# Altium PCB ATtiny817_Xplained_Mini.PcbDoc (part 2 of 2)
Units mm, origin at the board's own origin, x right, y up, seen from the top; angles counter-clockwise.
Board outline 60 x 75 mm, 4 copper layers (Top Layer, Ground Plane, Power Plane, Bottom Layer), stack 0.778 mm thick; 64 components, 81 nets, 498 pads, 125 vias.
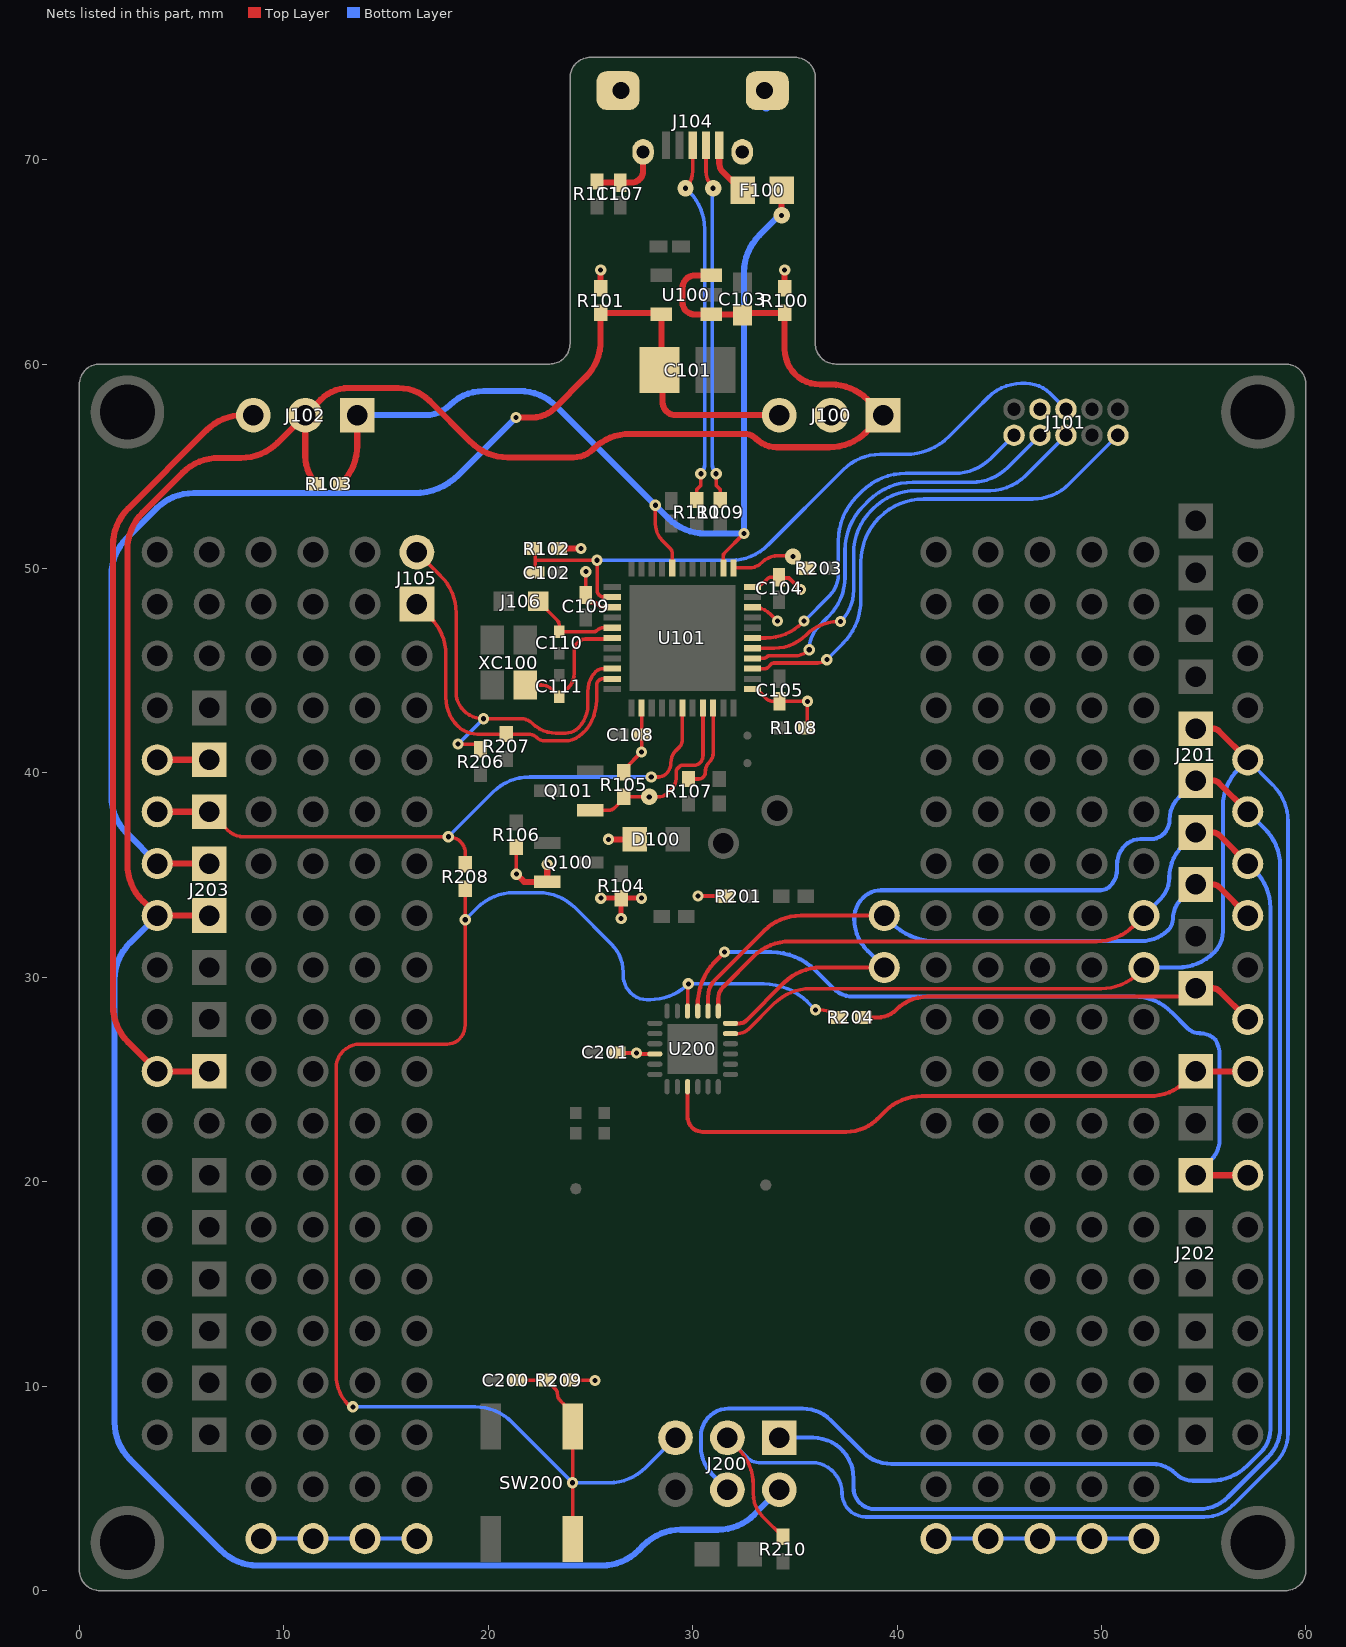
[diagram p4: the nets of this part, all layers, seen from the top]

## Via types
v1: diameter 0.55, hole 0.25, Top Layer to Bottom Layer, 103 vias
v2: diameter 0.55/0.8 (per signal layer), hole 0.25, Top Layer to Bottom Layer, tented top, 22 vias

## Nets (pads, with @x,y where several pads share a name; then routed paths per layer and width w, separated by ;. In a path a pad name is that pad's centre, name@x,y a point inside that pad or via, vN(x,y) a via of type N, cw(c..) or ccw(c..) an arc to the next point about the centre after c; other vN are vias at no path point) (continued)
PB7: J202.8 pad.12@57.15,25.4 U200.9 | length 30.2
  Top Layer w0.2: U200.9@29.75,24.64 29.75,23.177 ccw(c30.487,23.177) 30.487,22.441 37.504,22.441 ccw(c37.504,24.619) 38.602,22.737 ccw(c37.504,24.619) 39.045,23.079 39.408,23.442 cw(c41.204,21.646) 41.204,24.186 52.344,24.186 ccw(c52.344,26.726) 54.14,24.93 J202.8@54.61,25.4
  Top Layer w0.3: J202.8@54.61,25.4 pad.12@57.15,25.4
PC0_SPI_SCK: J200.3@31.7,7.48 J201.6@54.61,42.164 pad.10@52.07,30.48 pad.12@57.15,40.64 R210.2 U200.17 | length 108.2
  Top Layer w0.175: J200.3@31.7,7.48 32.219,6.961 cw(c30.423,5.164) 32.963,5.164 32.963,4.744 ccw(c34.554,4.744) 33.429,3.62 R210.2@34.417,2.632 ; U200.17@31.86,27.25 32.201,27.25 ccw(c32.201,28.012) 32.739,27.473 33.971,28.705 cw(c35.767,26.909) 35.767,29.449 49.987,29.449 ccw(c49.987,31.989) 51.783,30.193 pad.10@52.07,30.48
  Top Layer w0.3: J201.6@54.61,42.164 55.457,42.164 cw(c55.457,41.755) 55.746,42.044 pad.12@57.15,40.64
  Bottom Layer w0.175: J200.3@31.7,7.48 32.704,6.476 ccw(c33.225,6.997) 33.225,6.261 35.819,6.261 cw(c35.819,4.775) 37.305,4.775 ccw(c38.479,4.775) 38.479,3.601 55.027,3.601 ccw(c55.027,5.582) 56.428,4.181 58.542,6.295 ccw(c57.141,7.696) 59.122,7.696 59.122,37.616 ccw(c56.582,37.616) 58.378,39.412 pad.12@57.15,40.64
  Bottom Layer w0.2: pad.10@52.07,30.48 53.718,30.48 ccw(c53.718,33.02) 55.514,31.224 ccw(c54.492,32.247) 55.938,32.247 55.938,38.376 cw(c58.478,38.376) pad.12@56.682,40.172
PC1_SPI_MISO: J200.1@34.24,7.48 J201.5@54.61,39.624 pad.12@57.15,38.1 pad.@39.37,30.48 U200.18 | length 94.6
  Top Layer w0.2: U200.18@31.86,27.75 32.282,27.75 ccw(c32.282,28.249) 32.635,27.896 34.475,29.736 cw(c36.271,27.94) 36.271,30.48 pad.@39.37,30.48
  Top Layer w0.3: J201.5@54.61,39.624 55.457,39.624 cw(c55.457,39.215) 55.746,39.504 pad.12@57.15,38.1
  Bottom Layer w0.2: J200.1@34.24,7.48 35.885,7.48 cw(c35.885,5.499) 37.866,5.499 37.866,5.038 ccw(c38.918,5.038) 38.918,3.986 54.773,3.986 ccw(c54.773,5.968) 56.173,4.567 58.154,6.547 ccw(c56.753,7.948) 58.735,7.948 ; pad.@39.37,30.48 38.549,31.301 cw(c40.11,32.862) 37.902,32.862 cw(c39.355,32.862) 38.328,33.889 cw(c39.216,33.001) 39.216,34.257 49.943,34.257 ccw(c49.943,34.928) 50.417,34.454 ccw(c49.594,35.277) 50.758,35.277 50.758,35.513 cw(c52.079,35.513) 51.145,36.447 cw(c51.905,35.686) 51.905,36.762 52.42,36.762 ccw(c52.42,37.636) 53.039,37.018 ccw(c52.332,37.724) 53.331,37.724 cw(c54.831,37.724) 53.771,38.785 J201.5@54.61,39.624 ; pad.12@57.15,38.1 57.991,37.259 cw(c56.195,35.463) 58.735,35.463 58.735,8.026
PC2_SPI_MOSI: J200.4@31.7,4.94 J201.4@54.61,37.084 pad.10@52.07,33.02 pad.12@57.15,35.56 U200.19 | length 93.3
  Top Layer w0.2: U200.19@31.25,28.36 31.25,28.944 cw(c32.092,28.944) 31.497,29.539 32.976,31.018 cw(c34.772,29.222) 34.772,31.762 49.76,31.762 ccw(c49.76,34.302) 51.556,32.506 pad.10@52.07,33.02
  Top Layer w0.3: J201.4@54.61,37.084 55.457,37.084 cw(c55.457,36.675) 55.746,36.964 pad.12@57.15,35.56
  Bottom Layer w0.2: J200.4@31.7,4.94 30.983,5.657 cw(c32.384,7.058) 30.402,7.058 30.402,7.548 cw(c31.76,7.548) 31.76,8.906 35.369,8.906 cw(c35.369,6.925) 36.77,8.326 38.32,6.776 ccw(c39.721,8.177) 39.721,6.196 52.49,6.196 cw(c52.49,4.607) 53.613,5.731 ccw(c54.474,6.591) 54.474,5.374 55.34,5.374 ccw(c55.34,7.914) 57.136,6.118 57.793,6.776 ccw(c56.671,7.898) 58.258,7.898 58.258,33.4 ccw(c55.718,33.4) 57.514,35.196 pad.12@57.15,35.56 ; pad.10@52.07,33.02 52.877,33.827 ccw(c51.823,34.881) 53.313,34.881 cw(c55.502,34.881) 53.954,36.428 J201.4@54.61,37.084
PC3_SPI_SS: J201.3@54.61,34.544 pad.12@57.15,33.02 pad.@39.37,33.02 U200.20 | length 32
  Top Layer w0.2: U200.20@30.75,28.36 30.75,29.053 cw(c31.914,29.053) 31.091,29.876 33.491,32.276 cw(c35.287,30.48) 35.287,33.02 pad.@39.37,33.02 pad.@39.846,33.496
  Top Layer w0.3: J201.3@54.61,34.544 55.457,34.544 cw(c55.457,34.135) 55.746,34.424 pad.12@57.15,33.02
  Bottom Layer w0.2: pad.@39.37,33.02 39.728,32.662 ccw(c41.883,34.817) 41.883,31.769 51.933,31.769 ccw(c51.933,33.664) 53.273,32.324 ccw(c52.754,32.843) 53.488,32.843 cw(c54.885,32.843) 53.897,33.831 J201.3@54.61,34.544
PC4_PWM_W4: J202.6 pad.12@57.15,20.32 U200.21 | length 39.6
  Top Layer w0.2: U200.21@30.25,28.36 U200.21@30.25,28.666 ; 30.25,28.874 U200.21@30.25,28.666 ; 30.994,30.67 31.062,30.737 ; 31.348,31.024 31.062,30.737 ; v1(31.556,31.235) 31.143,30.822 ccw(c33.298,28.666) 31.062,30.737 ; J202.6@54.175,20.755 J202.6@54.61,20.32 ; U200.21@30.25,28.666 cw(c33.298,28.666) 31.062,30.737
  Top Layer w0.3: J202.6@54.61,20.32 pad.12@57.15,20.32
  Bottom Layer w0.2: v1(31.556,31.235) 33.844,31.235 cw(c33.844,28.187) 35.999,30.342 36.891,29.45 ccw(c37.847,30.407) 37.847,29.054 51.615,29.054 cw(c51.615,26.514) 53.411,28.31 54.213,27.508 ccw(c54.804,28.099) 54.804,27.264 54.824,27.264 cw(c54.824,26.219) 55.562,26.958 cw(c54.356,26.204) 55.779,26.204 55.779,22.072 cw(c54.371,22.072) 55.366,21.076 J202.6@54.61,20.32
PC5_BTN: C200.2 J200.5@29.16,7.48 R204.1 R208.1 R209.1 SW200.3 SW200.4 U200.22 | length 82.1
  Top Layer w0.175: v1(13.375,8.991) cw(c13.375,9.281) 13.171,9.076 cw(c14.656,10.562) 12.555,10.562 12.555,25.578 cw(c13.69,25.578) 12.888,26.38 cw(c13.734,25.534) 13.734,26.731 17.997,26.731 ccw(c17.997,27.558) 18.582,26.973 ccw(c17.882,27.673) 18.872,27.673 18.872,31.631 ; 18.875,31.633 v1(18.875,32.814) R208.1@18.875,34.325 ; C200.2@21.4,10.3 R209.1@22.85,10.3 23.285,9.865 cw(c23.043,9.624) 23.384,9.624 ccw(c23.839,9.624) 23.518,9.303 23.651,9.17 cw(c22.506,8.025) SW200.4@24.125,8.025 v1(24.125,5.275) SW200.3@24.125,2.525 ; U200.22@29.75,28.36 v1@29.75,29.554 ; v1(36.003,28.408) 36.24,28.408 cw(c36.24,27.139) R204.1@37.138,28.036
  Bottom Layer w0.175: v1(13.375,8.991) 19.357,8.991 cw(c19.357,6.451) 21.153,8.247 v1(24.125,5.275) 25.903,5.275 ccw(c25.903,7.815) 27.699,6.019 J200.5@29.16,7.48 ; v1(18.875,32.814) 19.459,33.398 cw(c21.255,31.602) 21.255,34.142 22.457,34.142 cw(c22.457,31.602) 24.253,33.398 26.033,31.618 cw(c24.671,30.256) 26.597,30.256 26.597,30.122 ccw(c27.847,30.122) 26.963,29.238 ccw(c27.762,30.036) 27.762,28.907 27.919,28.907 ccw(c27.919,31.549) 29.054,29.163 ccw(c27.919,31.549) v1(29.787,29.681) 33.468,29.681 cw(c33.468,26.633) 35.622,28.789 cw(c33.468,26.633) 35.624,28.788 v1(36.003,28.408)
PC5_PWM_W5: J201.1@54.61,29.464 pad.12@57.15,27.94 R204.2 | length 19.8
  Top Layer w0.2: R204.2@38.338,28.036 39.039,28.036 ccw(c39.039,29.351) 39.969,28.421 cw(c41.495,26.895) 41.495,29.054 53.62,29.054 ccw(c53.62,30.454) J201.1@54.61,29.464
  Top Layer w0.3: J201.1@54.61,29.464 55.457,29.464 cw(c55.457,29.055) 55.746,29.344 pad.12@57.15,27.94
PD2_UART_RXD1: J105.2@16.51,50.8 R206.1 U101.20 | length 21.3
  Top Layer w0.175: J105.2@16.51,50.8 17.681,49.629 cw(c15.885,47.833) 18.425,47.833 18.425,43.955 ccw(c19.705,43.955) 18.8,43.05 ccw(c19.766,44.016) v1(19.766,42.65) 21.607,42.65 cw(c21.607,41.882) 22.15,42.425 ccw(c23.311,43.586) 23.311,41.944 23.783,41.944 ccw(c23.783,42.831) 24.41,42.204 ccw(c23.288,43.326) 24.412,42.205 ccw(c23.288,43.326) 24.875,43.326 24.875,43.998 cw(c26.248,43.998) 25.277,44.968 cw(c25.595,44.651) 25.595,45.1 U101.20@26.075,45.1 ; v1(18.525,41.409) 19.366,41.409 R206.1@19.625,41.15
  Bottom Layer w0.175: v1(18.525,41.409) v1(19.766,42.65)
PD3_UART_TXD1: J105.1@16.51,48.26 R207.1 U101.21 | length 16.5
  Top Layer w0.175: J105.1@16.51,48.26 17.181,47.589 cw(c15.385,45.793) 17.925,45.793 17.925,43.688 ccw(c19.888,43.688) 18.5,42.3 ccw(c19.466,43.266) 19.466,41.9 R207.1@20.875,41.9 21.964,41.9 cw(c21.964,41.319) 22.374,41.73 ccw(c22.766,42.122) 22.766,41.568 23.74,41.568 ccw(c23.74,42.781) 24.598,41.923 24.6,41.925 ; 24.602,41.923 24.787,42.108 ccw(c22.945,43.576) 24.8,42.125 ccw(c22.945,43.576) 25.3,43.576 25.3,44.262 cw(c25.662,44.262) 25.406,44.518 cw(c25.604,44.32) 25.604,44.6 U101.21@26.075,44.6
POWER_ENABLE: Q101.1 R105.1 U101.30 | length 11.1
  Top Layer w0.175: Q101.1@24.985,38.17 25.902,38.17 ccw(c25.902,38.538) 25.962,38.175 ccw(c25.902,38.538) 26.162,38.278 26.565,38.681 ccw(c26.422,38.825) R105.1@26.625,38.825 v2(27.878,38.825) 28.306,38.825 ccw(c28.306,39.547) 28.817,39.036 28.967,39.187 ccw(c28.434,39.719) 29.187,39.719 29.187,40.016 cw(c29.507,40.016) 29.281,40.242 29.335,40.296 cw(c29.532,40.099) 29.532,40.378 30.09,40.378 ccw(c30.09,40.754) 30.356,40.488 ccw(c29.997,40.847) 30.505,40.847 30.505,43.17 U101.30@30.5,43.175 30.5,41.501
RESET_SENSE: J203.3@6.35,38.1 pad.0@3.81,38.1 R208.2 U101.28 | length 31.8
  Top Layer w0.175: J203.3@6.35,38.1 7.239,37.211 ccw(c8.05,38.022) 8.05,36.875 v1(18.046,36.875) cw(c18.046,36.021) 18.65,36.625 cw(c18.107,36.082) 18.875,36.082 R208.2@18.875,35.525 ; v1(27.975,39.8) 28.334,39.8 ccw(c28.334,40.326) 28.706,39.954 ccw(c28.163,40.497) 28.931,40.497 cw(c29.78,40.497) 29.18,41.097 29.353,41.27 ccw(c28.997,41.625) 29.5,41.625 U101.28@29.5,43.175
  Top Layer w0.3: pad.0@3.81,38.1 J203.3@6.35,38.1
  Bottom Layer w0.175: v1(18.046,36.875) 20.227,39.056 cw(c22.024,37.26) 22.024,39.8 v1(27.975,39.8)
S\R\S\T\: C102.2 J101.6 R102.1 U101.13 | length 33.1
  Top Layer w0.175: R102.1@22.25,50.975 cw(c22.129,50.854) 22.3,50.854 22.3,50.4 ; C102.2@22.3,49.8 22.3,50.4 ; U101.13@26.075,48.6 25.666,48.6 cw(c25.666,48.941) 25.425,48.7 cw(c25.666,48.941) 25.325,48.941 v1(25.325,50.4) 22.3,50.4
  Bottom Layer w0.175: v1(25.325,50.4) 31.885,50.4 ccw(c31.885,52.94) 33.682,51.144 37.37,54.833 cw(c39.166,53.036) 39.166,55.576 40.401,55.576 ccw(c40.401,58.624) 42.556,56.469 43.844,57.757 44.472,58.385 cw(c46.085,56.773) 46.085,59.053 46.298,59.053 cw(c46.298,57.379) 47.482,58.563 J101.6@48.26,57.785
SHIELD: C107.2 J104.6@33.512,73.375 J104.7@26.488,73.375 J104.8@32.425,70.375 J104.9@27.575,70.375 R111.1 | length 5.1
  Top Layer w0.3: R111.1@25.315,68.926 ccw(c25.436,69.047) 25.436,68.876 C107.2@26.458,68.876 27.008,68.876 ccw(c27.008,69.445) 27.411,69.043 ccw(c27.015,69.439) 27.575,69.439 J104.9@27.575,70.375 ; J104.6@33.6,72.585 J104.6@33.6,73.375
  Bottom Layer w0.5: J104.6@33.6,72.602 J104.6@33.6,73.375
STATUS_LED: R107.2 U101.31 | length 4.3
  Top Layer w0.175: R107.2@29.8,39.7 30.306,39.7 ccw(c30.306,39.995) 30.515,39.787 ccw(c30.259,40.042) 30.621,40.042 cw(c31.341,40.042) 30.648,40.238 cw(c31.341,40.042) 30.832,40.552 ccw(c30.426,40.958) 30.908,40.645 ccw(c30.426,40.958) 31,40.958 U101.31@31,43.175
TCK: J101.1 U101.39 | length 18.4
  Top Layer w0.175: U101.39@32.925,46.6 33.573,46.6 ccw(c33.573,49.14) 35.369,47.344 v1(35.45,47.425)
  Bottom Layer w0.175: v1(35.45,47.425) 36.693,48.668 ccw(c35.653,49.709) 37.125,49.709 37.125,51.358 cw(c40.173,51.358) 38.017,53.513 38.267,53.762 cw(c40.422,51.607) 40.422,54.655 42.817,54.655 ccw(c42.817,57.172) 44.597,55.392 J101.1@45.72,56.515
TDI: J101.9 U101.36 | length 26.2
  Top Layer w0.175: U101.36@32.925,45.1 33.525,45.1 ccw(c33.525,45.341) 33.696,45.171 33.85,45.325 ; 33.85,45.325 cw(c33.971,45.204) 33.971,45.375 36.128,45.375 ccw(c36.128,45.972) 36.55,45.55 v1(36.562,45.538)
  Bottom Layer w0.175: v1(36.562,45.538) 37.334,46.31 ccw(c35.179,48.465) 37.335,46.311 ccw(c35.179,48.465) 38.043,47.423 ccw(c35.179,48.465) 38.227,48.465 38.227,50.326 cw(c41.275,50.326) 39.119,52.481 39.143,52.505 cw(c41.298,50.349) 41.298,53.397 46.63,53.397 ccw(c46.63,55.937) 47.102,53.442 ; J101.9@50.8,56.515 48.426,54.141 ; 47.102,53.442 ccw(c46.63,55.937) 48.426,54.141 ; 47.102,53.442 ccw(c46.63,55.937) 48.426,54.141
TDO: J101.3 U101.37 | length 22.5
  Top Layer w0.175: U101.37@32.925,45.6 33.444,45.6 ccw(c33.444,45.856) 33.625,45.675 cw(c33.746,45.554) 33.746,45.725 34.976,45.725 ccw(c34.976,46.749) v1(35.7,46.025)
  Bottom Layer w0.175: v1(35.7,46.025) cw(c37.33,46.025) 36.177,47.177 36.5,47.5 ccw(c34.75,49.25) 36.6,47.606 36.653,47.659 ccw(c34.73,49.582) 37.45,49.582 37.45,50.891 cw(c40.498,50.891) 38.342,53.047 38.62,53.324 cw(c40.775,51.169) 40.775,54.217 43.654,54.217 ; J101.3@46.99,56.515 45.426,54.951 ; 43.654,54.217 ccw(c43.654,56.722) 45.426,54.951 ; 43.654,54.217 ccw(c43.654,56.722) 45.426,54.951
TMS: J101.5 U101.38 | length 21.3
  Top Layer w0.175: U101.38@32.925,46.1 33.981,46.1 ccw(c33.981,48.319) 35.55,46.75 cw(c37.119,45.181) 37.119,47.4 v1(37.236,47.4)
  Bottom Layer w0.175: v1@37.237,47.401 ccw(c35.698,48.938) 37.672,48.025 ccw(c35.698,48.938) 37.873,48.938 37.873,50.722 cw(c40.921,50.722) 38.766,52.877 38.804,52.914 cw(c40.959,50.759) 40.959,53.807 44.5,53.807 ccw(c44.5,56.347) 44.556,53.808 ccw(c44.5,56.347) 46.296,54.551 J101.5@48.26,56.515
UPDI: R203.1 U101.1 | length 4.1
  Top Layer w0.175: U101.1@32,50.025 32.736,50.025 ccw(c32.736,50.964) 33.4,50.3 cw(c34.185,49.515) 34.185,50.625 34.55,50.625 cw(c34.55,49.9) 35.275,49.9 R203.1@35.55,49.9
  other v2: 34.908,50.583
USB_VBUS: F100.1 J104.1 | length 2.7
  Top Layer w0.3: J104.1@31.3,70.7 31.3,69.822 ccw(c31.897,69.822) 31.475,69.4 32.322,68.553 ccw(c32.45,68.681) F100.1@32.45,68.5
USBD_N: J104.2 R109.1 | length 17.6
  Top Layer w0.18: J104.2@30.65,70.7 30.65,69.445 ccw(c31.845,69.445) v2(31,68.6) ; v1(31.15,54.635) 31.15,54.062 31.35,53.862 R109.1@31.35,53.35
  Bottom Layer w0.18: v2(31,68.6) ccw(c31.084,68.516) 30.965,68.516 30.965,55.082 ccw(c31.597,55.082) v1(31.15,54.635) v1@31.15,54.684
USBD_P: J104.3 R110.1 | length 17.9
  Top Layer w0.18: v2(29.65,68.6) ccw(c28.805,69.445) 30,69.445 J104.3@30,70.7 ; R110.1@30.2,53.35 30.2,53.862 30.4,54.062 v1(30.4,54.635)
  Bottom Layer w0.18: v2(29.65,68.6) 29.841,68.409 cw(c28.045,66.613) 30.585,66.613 30.585,55.082 cw(c29.953,55.082) v1(30.4,54.635)
VCC_BOARD: C104.2 C105.1 C108.2 C109.1 D100.2 J100.2 J101.4 Q100.2 R100.1 R101.2 R102.2 R105.2 R106.2 R108.2 U101.14 U101.24 U101.34 U101.42 U101.44 | length 22.9
  Top Layer w0.175: v1(21.375,35.046) R106.2@21.375,36.375 ; v1(24.775,49.844) C109.1@24.775,48.7 24.775,48.336 25.201,48.336 cw(c25.201,48.175) 25.315,48.289 25.443,48.16 ccw(c25.589,48.306) 25.589,48.1 U101.14@26.075,48.1 ; R105.2@26.625,40.025 cw(c26.916,40.025) 26.71,40.231 v1(27.5,41.021) C108.2@27.5,41.875 U101.24@27.5,43.175 ; U101.34@32.925,44.1 cw(c32.925,43.617) 33.266,43.959 33.575,43.65 ccw(c33.937,44.012) 33.937,43.5 C105.1@34.25,43.5 v1(35.615,43.5) 35.615,42.356 cw(c35.394,42.356) R108.2@35.55,42.2 ; U101.42@32.925,48.1 32.98,48.1 cw(c32.98,46.905) 33.825,47.75 v1(34.15,47.425) ; U101.44@32.925,49.1 ccw(c32.925,49.926) 33.509,49.342 33.661,49.493 cw(c33.858,49.296) 33.858,49.575 C104.2@34.225,49.575
  Top Layer w0.2: C104.2@34.225,49.575 ccw(c34.303,49.653) 34.303,49.543 34.631,49.543 cw(c34.631,49.357) 34.762,49.488 v1(35.275,48.975)
  Top Layer w0.3: v1(21.375,35.046) 21.751,34.67 Q100.2@22.885,34.67 v1(22.885,35.515) ; R102.2@23.45,50.975 v1(24.54,50.975) ; R101.2@25.5,63.7 v1(25.5,64.602) ; v1(25.885,36.75) D100.2@27.175,36.75 ; R100.1@34.5,63.7 v1(34.5,64.603)
  Bottom Layer w0.3: v1(34.5,64.603) cw(c34.557,64.603) v1@34.557,64.66
VCC_P3V3: C101.1 J100.3 J203.4@6.35,35.56 pad.0@3.81,35.56 R101.1 U100.5 | length 61.8
  Top Layer w0.3: pad.0@3.81,35.56 J203.4@6.35,35.56 ; v1(21.354,57.383) 22.142,57.383 ccw(c22.142,58.952) 23.252,57.842 24.756,59.347 ccw(c22.96,61.143) 25.5,61.143 R101.1@25.5,62.5 U100.5@28.398,62.5 ; J100.3@34.235,57.5 29.174,57.5 cw(c29.174,58.145) 28.529,58.145 28.529,59.121 ccw(c28.43,59.121) 28.43,59.22 28.43,59.714 ccw(c28.339,59.805) 28.468,59.805 U100.5@28.468,62.431 ; U100.5@28.398,62.5 cw(c28.398,62.431) U100.5@28.468,62.431 ; U100.5@28.398,62.5 U100.5@28.468,62.431
  Bottom Layer w0.3: pad.0@3.81,35.56 2.308,37.062 cw(c4.104,38.858) 1.564,38.858 1.564,49.674 cw(c4.104,49.674) 2.308,51.47 3.781,52.943 cw(c5.577,51.147) 5.577,53.687 16.395,53.687 ccw(c16.395,56.735) 18.551,54.58 v1(21.354,57.383)
VCC_P5V0: C103.1 J100.1 J102.2 J200.2@34.24,4.94 J203.5@6.35,33.02 pad.0@3.81,33.02 R100.2 R103.2 U100.1 U100.3 | length 145.6
  Top Layer w0.3: J203.5@6.35,33.02 pad.0@3.81,33.02 3.094,33.736 cw(c4.89,35.532) 2.35,35.532 2.35,50.928 cw(c4.89,50.928) 3.094,52.724 5.038,54.668 cw(c6.834,52.872) 6.834,55.412 7.91,55.412 ccw(c7.91,57.952) 9.706,56.156 J102.2@11.05,57.5 ; R103.2@11.6,54.15 cw(c12.928,55.478) 11.05,55.478 J102.2@11.05,57.5 ; U100.3@30.918,64.337 30.111,64.337 ccw(c30.111,63.73) 29.505,63.73 29.505,63.01 ccw(c30.084,63.01) 30.084,62.431 U100.1@30.918,62.431 32.386,62.431 C103.1@32.436,62.381 cw(c32.724,62.092) 32.724,62.5 R100.2@34.5,62.5 34.5,60.724 ccw(c36.223,60.724) 36.223,59.001 36.762,59.001 cw(c36.762,56.461) 38.558,58.257 J100.1@39.315,57.5 38.49,56.675 cw(c36.694,58.471) 36.694,55.931 34.11,55.931 cw(c34.11,57.375) 33.089,56.354 ccw(c32.533,55.798) 32.533,56.584 26.934,56.584 ccw(c26.934,54.044) 25.138,55.84 cw(c24.16,56.819) 24.16,55.435 20.948,55.435 cw(c20.948,57.975) 19.152,56.179 17.139,58.191 ccw(c15.61,56.662) 15.61,58.825 13.174,58.825 ccw(c13.174,56.896) 11.81,58.26 J102.2@11.05,57.5
  Bottom Layer w0.3: pad.0@3.81,33.02 2.466,31.676 ccw(c4.262,29.88) 1.722,29.88 1.722,8.226 ccw(c4.262,8.226) 2.466,6.43 6.925,1.971 ccw(c8.721,3.768) 8.721,1.228 25.557,1.228 ccw(c25.557,3.768) 27.353,1.971 27.618,2.237 cw(c29.414,0.44) 29.414,2.98 31.228,2.98 ccw(c31.228,5.52) 33.024,3.724 J200.2@34.24,4.94
VCC_TARGET: C201.2 J203.2@6.35,40.64 pad.0@3.81,40.64 pad.2@8.89,2.54 pad.3@11.43,2.54 pad.4@13.97,2.54 pad.5@16.51,2.54 pad.6@41.91,2.54 pad.7@44.45,2.54 pad.8@46.99,2.54 pad.9@49.53,2.54 pad.10@52.07,2.54 R104.2 R201.2 R209.2 U200.4 | length 28.7
  Top Layer w0.175: R209.2@24.05,10.3 25.165,10.3 cw(c25.165,10.215) v1(25.225,10.275)
  Top Layer w0.2: C201.2@26.3,26.3 v1(27.25,26.3) 27.3,26.25 U200.4@28.14,26.25 ; v1(30.265,33.972) R201.2@31.619,33.972
  Top Layer w0.25: v1(25.509,33.873) R104.2@26.502,33.873 ; v1(26.502,32.88) R104.2@26.502,33.873 ; v1(27.495,33.873) R104.2@26.502,33.873
  Top Layer w0.3: pad.0@3.81,40.64 J203.2@6.35,40.64 J203.2@5.669,39.959
  Bottom Layer w0.2: pad.2@8.89,2.54 pad.3@11.43,2.54 pad.4@13.97,2.54 pad.5@16.51,2.54 ; v1@27.25,26.263 v1(27.25,26.3) ; v1@30.226,33.956 cw(c30.265,33.918) v1(30.265,33.972) ; pad.6@41.91,2.54 pad.7@44.45,2.54 pad.8@46.99,2.54 pad.9@49.53,2.54 pad.10@52.07,2.54
VCC_VBUS: F100.2 J102.1 R103.1 U101.2 U101.7 | length 48.4
  Top Layer w0.175: v1(28.175,53.092) 28.175,52.2 ccw(c29.382,52.2) 28.528,51.347 28.9,50.975 cw(c28.659,50.734) 29,50.734 U101.7@29,50.025 ; U101.2@31.5,50.025 31.5,50.629 cw(c31.671,50.629) 31.55,50.75 ; 31.55,50.75 v1(32.512,51.712)
  Top Layer w0.3: R103.1@12.8,54.15 12.846,54.196 ccw(c11.05,55.992) 13.59,55.992 J102.1@13.59,57.5 ; v2(34.35,67.275) F100.2@34.35,68.5
  Bottom Layer w0.3: J102.1@13.59,57.5 16.928,57.5 ccw(c16.928,59.191) 18.124,57.995 cw(c19.773,56.346) 19.773,58.678 21.537,58.678 cw(c21.537,56.138) 23.333,57.934 v1(28.175,53.092) 28.812,52.456 ccw(c30.608,54.252) 30.608,51.712 v1(32.512,51.712) 32.512,64.493 cw(c35.052,64.493) 33.256,66.289 34.241,67.275 v2(34.35,67.275)
VCC_VIN: J102.3 J203.8@6.35,25.4 pad.0@3.81,25.4 | length 39
  Top Layer w0.3: J203.8@6.35,25.4 pad.0@3.81,25.4 2.387,26.823 cw(c4.183,28.619) 1.643,28.619 1.643,51.136 cw(c4.183,51.136) 2.387,52.932 6.211,56.756 cw(c8.007,54.96) 8.007,57.5 J102.3@8.51,57.5
XTAL1: C111.1 U101.17 XC100.1 | length 6.5
  Top Layer w0.175: XC100.1@21.9,44.3 22.598,44.3 cw(c22.598,43.571) 23.113,44.087 C111.1@23.475,43.725 23.923,44.173 ccw(c23.243,44.853) 23.928,44.178 ccw(c23.243,44.853) 24.205,44.853 24.205,46.034 cw(c24.616,46.034) 24.325,46.325 24.409,46.409 cw(c24.75,46.067) 24.75,46.55 25.954,46.55 ccw(c25.954,46.721) U101.17@26.075,46.6
XTAL2: C110.2 J106.2 U101.16 | length 4.7
  Top Layer w0.175: J106.2@22.535,48.365 ccw(c22.45,48.279) J106.2@22.45,48.4 22.45,48.391 23.374,47.467 cw(c23.129,47.223) 23.475,47.223 C110.2@23.475,46.9 25.144,46.9 ccw(c25.144,47.156) 25.325,46.975 cw(c25.627,46.673) 25.627,47.1 U101.16@26.075,47.1
pads on no net: J104.6@33.6,73.375 J104.7@26.4,73.375 J104.8@32.425,70.375 J104.9@27.575,70.375 J105.1@16.51,48.26 J105.2@16.51,50.8 J200.1@34.24,7.48 J200.2@34.24,4.94 J200.3@31.7,7.48 J200.4@31.7,4.94 J200.5@29.16,7.48 J200.6@29.16,4.94 J201.1@54.61,29.464 J201.2@54.61,32.004 J201.3@54.61,34.544 J201.4@54.61,37.084 J201.5@54.61,39.624 J201.6@54.61,42.164 J201.7@54.61,44.704 J201.8@54.61,47.244 J201.9@54.61,49.784 J201.10@54.61,52.324 J203.1@6.35,43.18 J203.2@6.35,40.64 J203.3@6.35,38.1 J203.4@6.35,35.56 J203.5@6.35,33.02 J203.6@6.35,30.48 J203.7@6.35,27.94 J203.8@6.35,25.4 J204.1@6.35,20.32 J204.2@6.35,17.78 J204.3@6.35,15.24 J204.4@6.35,12.7 J204.5@6.35,10.16 J204.6@6.35,7.62
copper on no net: | length 228.6
  Top Layer w0.3: 3.81,22.86 6.35,22.86 ; 3.81,45.72 6.35,45.72 ; 3.81,48.26 6.35,48.26 ; 3.81,50.8 6.35,50.8 ; 8.89,7.62 11.43,7.62 ; 8.89,10.16 11.43,10.16 ; 8.89,12.7 11.43,12.7 ; 8.89,15.24 11.43,15.24 ; 8.89,17.78 11.43,17.78 ; 8.89,20.32 11.43,20.32 ; 8.89,22.86 11.43,22.86 ; 8.89,25.4 11.43,25.4 ; 8.89,27.94 11.43,27.94 ; 8.89,30.48 11.43,30.48 ; 8.89,33.02 11.43,33.02 ; 8.89,35.56 11.43,35.56 ; 8.89,38.1 11.43,38.1 ; 8.89,45.72 11.43,45.72 ; 8.89,48.26 11.43,48.26 13.97,48.26 ; 8.89,50.8 11.43,50.8 13.97,50.8 ; 13.97,7.62 16.51,7.62 ; 13.97,10.16 16.51,10.16 ; 13.97,12.7 16.51,12.7 ; 13.97,15.24 16.51,15.24 ; 13.97,17.78 16.51,17.78 ; 13.97,20.32 16.51,20.32 ; 13.97,22.86 16.51,22.86 ; 13.97,25.4 16.51,25.4 ; 13.97,27.94 16.51,27.94 ; 13.97,30.48 16.51,30.48 ; 13.97,33.02 16.51,33.02 ; 13.97,35.56 16.51,35.56 ; 13.97,38.1 16.51,38.1 ; 13.97,40.64 16.51,40.64 ; 13.97,43.18 16.51,43.18 ; 13.97,45.72 16.51,45.72 ; 41.91,7.62 44.45,7.62 ; 41.91,10.16 44.45,10.16 ; 41.91,22.86 44.45,22.86 ; 41.91,25.4 44.45,25.4 ; 41.91,27.94 44.45,27.94 ; 41.91,30.48 44.45,30.48 ; 41.91,33.02 44.45,33.02 ; 41.91,35.56 44.45,35.56 ; 41.91,38.1 44.45,38.1 ; 41.91,40.64 44.45,40.64 ; 41.91,43.18 44.45,43.18 ; 41.91,45.72 44.45,45.72 ; 41.91,48.26 44.45,48.26 ; 41.91,50.8 44.45,50.8 ; 46.99,7.62 52.07,7.62 ; 46.99,10.16 52.07,10.16 ; 46.99,12.7 52.07,12.7 ; 46.99,15.24 52.07,15.24 ; 46.99,17.78 52.07,17.78 ; 46.99,20.32 52.07,20.32 ; 46.99,22.86 52.07,22.86 ; 46.99,25.4 52.07,25.4 ; 46.99,27.94 52.07,27.94 ; 46.99,30.48 49.53,30.48 ; 46.99,33.02 49.53,33.02 ; 46.99,35.56 52.07,35.56 ; 46.99,38.1 52.07,38.1 ; 46.99,40.64 52.07,40.64 ; 46.99,43.18 52.07,43.18 ; 46.99,45.72 52.07,45.72 ; 46.99,48.26 52.07,48.26 ; 46.99,50.8 52.07,50.8 ; 8.89,40.64 11.43,40.64 8.89,40.64 ; 8.89,43.18 11.43,43.18 8.89,43.18

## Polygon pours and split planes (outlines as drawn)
no net on Top Overlay "Bottom Layer LF-signals-No Net" (solid, pour order 8): 56,0.2 59.2,0.2 ccw(c59.2,0.7) 59.7,0.7 59.7,3.9 ccw(c59.2,3.9) 59.2,4.4 56,4.4 ccw(c56,3.9) 55.5,3.9 55.5,0.7 ccw(c56,0.7) 56,0.2
GND on Top Layer "Top GND" (solid, remove dead copper, pour order 13): 0,0 0,60 24,60 24,75 36,75 36,60 60,60 60,0
SHIELD on Top Layer "Bottom Layer LF-signals-No Net" (solid, remove dead copper, pour order 10): 25.25,69.7 24.92,69.7 cw(c24.92,70.372) 24.249,70.372 24.249,73.749 cw(c25.25,73.749) 25.25,74.75 34.75,74.75 cw(c34.75,73.75) 35.75,73.75 35.75,70.7 cw(c34.75,70.7) 34.75,69.7
GND on Bottom Layer "Bottom GND" (solid, remove dead copper, pour order 15): 0,0 0,60 24,60 24,75 36,75 36,60 60,60 60,0 42.5,0 42.5,21.75 17.525,21.75 17.525,10.75 44.46,10.75 44.46,0
GND on Bottom Layer "Bottom Layer-No Net" (hatched 45Degree grid 2 track 0.2, pour order 19): 17.525,21.75 42.5,21.75 42.5,10.75 17.525,10.75
GND on Bottom Layer "Bottom Filler" (solid, pour order 21): 41.262,11.061 41.262,0 47.081,0 47.081,11.061
PA6_PTC2 on Ground Plane (split plane): 27.005,20.253 27.005,12.244 17.025,12.244 19.014,12.244 19.014,20.253
PA7_PTC3 on Ground Plane (split plane): 41.005,20.253 41.005,12.244 31.025,12.244 33.014,12.244 33.014,20.253
GND on Ground Plane (split plane): 35.096,74.482 35.188,74.454 35.273,74.409 35.348,74.348 35.409,74.273 35.454,74.188 35.482,74.096 35.491,74.012 35.49,74 35.49,61 35.49,60.998 35.499,60.831 35.527,60.664 35.574,60.501 35.639,60.345 35.721,60.196 35.819,60.058 35.932,59.932 36.058,59.819 36.196,59.721 36.345,59.639 36.501,59.574 36.664,59.527 36.831,59.499 36.998,59.49 37,59.49 59,59.49 59.012,59.491 59.096,59.482 59.188,59.454 59.273,59.409 59.348,59.348 59.409,59.273 59.454,59.188 59.482,59.096 59.491,59.012 59.49,59 59.49,1 59.491,0.988 59.482,0.904 59.454,0.812 59.409,0.727 59.348,0.652 59.273,0.591 59.188,0.546 59.096,0.518 59.012,0.509 59,0.51 1,0.51 0.988,0.509 0.904,0.518 0.812,0.546 0.727,0.591 0.652,0.652 0.591,0.727 0.546,0.812 0.518,0.904 0.509,0.988 0.51,1 0.51,59 0.509,59.012 0.518,59.096 0.546,59.188 0.591,59.273 0.652,59.348 0.727,59.409 0.812,59.454 0.904,59.482 0.988,59.491 1,59.49 23,59.49 23.002,59.49 23.169,59.499 23.336,59.527 23.499,59.574 23.655,59.639 23.804,59.721 23.942,59.819 24.068,59.932 24.181,60.058 24.279,60.196 24.361,60.345 24.426,60.501 24.473,60.664 24.501,60.831 24.51,60.998 24.51,61 24.51,74 24.509,74.012 24.518,74.096 24.546,74.188 24.591,74.273 24.652,74.348 24.727,74.409 24.812,74.454 24.904,74.482 24.988,74.491 25,74.49 35,74.49 35.012,74.491
VCC_BOARD on Power Plane (split plane): 35.096,74.482 35.188,74.454 35.273,74.409 35.348,74.348 35.409,74.273 35.454,74.188 35.482,74.096 35.491,74.012 35.49,74 35.49,61 35.49,60.998 35.499,60.831 35.527,60.664 35.574,60.501 35.639,60.345 35.721,60.196 35.819,60.058 35.932,59.932 36.058,59.819 36.196,59.721 36.345,59.639 36.501,59.574 36.664,59.527 36.831,59.499 36.998,59.49 37,59.49 59,59.49 59.012,59.491 59.096,59.482 59.188,59.454 59.273,59.409 59.348,59.348 59.409,59.273 59.454,59.188 59.482,59.096 59.491,59.012 59.49,59 59.49,34.616 59.461,34.62 20.28,34.62 10.242,44.659 10.21,44.683 10.195,44.689 10.174,44.698 10.135,44.703 0.51,44.703 0.51,59 0.509,59.012 0.518,59.096 0.546,59.188 0.591,59.273 0.652,59.348 0.727,59.409 0.812,59.454 0.904,59.482 0.988,59.491 1,59.49 23,59.49 23.002,59.49 23.169,59.499 23.336,59.527 23.499,59.574 23.655,59.639 23.804,59.721 23.942,59.819 24.068,59.932 24.181,60.058 24.279,60.196 24.361,60.345 24.426,60.501 24.473,60.664 24.501,60.831 24.51,60.998 24.51,61 24.51,74 24.509,74.012 24.518,74.096 24.546,74.188 24.591,74.273 24.652,74.348 24.727,74.409 24.812,74.454 24.904,74.482 24.988,74.491 25,74.49 35,74.49 35.012,74.491
VCC_TARGET on Power Plane (split plane): 20.111,34.361 20.142,34.337 20.179,34.322 20.218,34.317 59.398,34.317 59.49,34.226 59.49,1 59.491,0.988 59.482,0.904 59.454,0.812 59.409,0.727 59.348,0.652 59.273,0.591 59.188,0.546 59.096,0.518 59.012,0.509 59,0.51 1,0.51 0.988,0.509 0.904,0.518 0.812,0.546 0.727,0.591 0.652,0.652 0.591,0.727 0.546,0.812 0.518,0.904 0.509,0.988 0.51,1 0.51,44.4 10.072,44.4

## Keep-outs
Keep-Out Layer:
  lines w0.1: 0.3,1.3 ccw(c1.3,1.3) 1.3,0.3 58.7,0.3 ccw(c58.7,1.3) 59.7,1.3 59.7,58.75 ccw(c58.7,58.75) 58.7,59.75 36.75,59.75 cw(c36.75,60.75) 35.75,60.75 35.75,73.75 ccw(c34.75,73.75) 34.75,74.75 25.25,74.75 ccw(c25.25,73.75) 24.25,73.75 24.25,60.75 cw(c23.25,60.75) 23.25,59.75 1.3,59.75 ccw(c1.3,58.75) 0.3,58.75 0.3,1.3

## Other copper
Top Layer:
  pour cut-out: 31.025,21.75 42.5,21.75 42.5,10.75 31.025,10.75
  pour cut-out: 17.525,21.75 29.012,21.75 29.012,10.75 17.525,10.75
  pour cut-out: 27.15,57.95 27.15,61.702 30.15,61.702 30.15,57.95
  pour cut-out: 27.693,61.634 27.693,65.134 31.711,65.134 31.711,61.631
  pour cut-out: 20,47.675 23.2,47.675 23.2,49.125 20,49.125
Power Plane (plane layer: these items are gaps in the copper):
  rectangle: 17.525,10.75 29.012,21.75
  rectangle: 31.025,10.75 42.5,21.75
  lines w0.3: 0,44.552 10.135,44.552 20.218,34.468 59.461,34.468 59.817,34.112

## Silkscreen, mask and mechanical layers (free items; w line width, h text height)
Top Overlay:
  drawing of 175 lines, arcs and shapes, not listed
  text "VIN" at 7.85,59.15 h1.1
  text "VBUS" at 12.4,59.15 h1.1
  text "3V3" at 33.401,59.15 h1.1
  text "5V0" at 38.35,59.15 h1.1
  text "11" at 53.9,54.9 h1.52
  text "GND" at 56.185,54.788 h1.52
  text "GND" at 0.914,54.661 h1.52
  text "ATTINY817" at 17.38,54.597 h2
  text "X" at 28.718,54.569 h4
  text "PLAINED" at 32.109,54.569 h2
  text "MINI" at 41.175,54.569 h1
  text "0" at 3.5,52.4 h1.52
  text "1" at 6.04,52.4 h1.52
  text "2" at 8.58,52.4 h1.52
  text "3" at 11.12,52.4 h1.52
  text "4" at 13.66,52.4 h1.52
  text "5" at 16.2,52.4 h1.52
  text "6" at 41.6,52.4 h1.52
  text "7" at 44.14,52.4 h1.52
  text "8" at 46.68,52.4 h1.52
  text "9" at 49.22,52.4 h1.52
  text "10" at 51.26,52.4 h1.52
  text "12" at 56.34,52.4 h1.52
  text "mEDBG" at 24.2,51 h1.3
  text "R" at 39.79,50.408 h1.52
  text "RX" at 18.199,50.343 h1.52
  text "PA2" at 59.202,49.742 h1.3 r90
  text "Q" at 39.79,47.774 h1.52
  text "TX" at 18.2,47.7 h1.52
  text "PA1" at 59.202,47.293 h1.3 r90
  text "P" at 17.849,45.361 h1.52
  text "P" at 39.79,45.361 h1.52
  text "O" at 17.849,42.719 h1.52
  text "O" at 39.79,42.719 h1.52
  text "NC" at 2.169,42.413 h1.3 r90
  text "GND" at 59.202,41.95 h1.3 r90
  text "BOOT" at 28.45,41.1 h1.4
  text "N" at 17.849,40.246 h1.52
  text "N" at 39.79,40.246 h1.52
  text "PC0" at 59.189,39.587 h1.3 r90
  text "VCC" at 2.169,39.47 h1.3 r90
  text "PA0" at 35.291,37.685 h1.52
  text "M" at 17.849,37.646 h1.52
  text "M" at 39.79,37.646 h1.52
  text "PC1" at 59.2,37.121 h1.3 r90
  text "RST" at 2.169,37.019 h1.3 r90
  text "EXT_CLK" at 32.715,36.096 h1.52
  text "L" at 39.79,35.223 h1.52
  text "3V3" at 2.169,34.56 h1.3 r90
  text "PC2" at 59.193,34.502 h1.3 r90
  text "K" at 17.849,32.619 h1.52
  text "5V" at 2.169,32.349 h1.3 r90
  text "PC3" at 59.194,31.966 h1.3 r90
  text "J" at 17.85,30.168 h1.52
  text "PA0" at 59.194,29.426 h1.3 r90
  text "GND" at 2.169,29.35 h1.3 r90
  text "B" at 22.381,29.15 h10
  text "I" at 17.849,27.845 h1.52
  text "I" at 39.79,27.845 h1.52
  text "PC5" at 59.195,26.893 h1.3 r90
  text "GND" at 2.169,26.61 h1.3 r90
  text "H" at 17.849,25.003 h1.52
  text "H" at 39.79,25.003 h1.52
  text "VIN" at 2.169,24.374 h1.3 r90
  text "PB7" at 59.187,24.338 h1.3 r90
  text "G" at 17.849,22.41 h1.52
  text "G" at 39.79,22.41 h1.52
  text "ATtiny817" at 26.576,22.367 h1.52
  text "PB6" at 59.187,21.798 h1.3 r90
  text "QT BTN 1" at 20.339,20.669 h1.5
  text "QT BTN 2" at 34.339,20.669 h1.5
  text "F" at 17.849,19.992 h1.52
  text "F" at 44.856,19.992 h1.52
  text "PA4" at 2.169,19.263 h1.3 r90
  text "PC4" at 59.189,19.251 h1.3 r90
  text "E" at 17.849,17.417 h1.52
  text "E" at 44.856,17.417 h1.52
  text "PA5" at 2.169,16.734 h1.3 r90
  text "PA3" at 59.2,16.738 h1.3 r90
  text "D" at 17.849,14.837 h1.52
  text "D" at 44.856,14.837 h1.52
  text "C" at 19.148,14.444 h3.8
  text "C" at 33.148,14.444 h3.8
  text "PA6" at 2.169,14.193 h1.3 r90
  text "PB5" at 59.193,14.194 h1.3 r90
  text "C" at 17.849,12.28 h1.52
  text "C" at 44.856,12.28 h1.52
  text "PA7" at 2.169,11.646 h1.3 r90
  text "PB4" at 59.194,11.643 h1.3 r90
  text "B" at 17.849,9.768 h1.52
  text "B" at 39.79,9.768 h1.52
  text "PB1" at 2.169,9.193 h1.3 r90
  text "SPI" at 30.734,9.119 h1.52
  text "PB2" at 59.194,9.114 h1.3 r90
  text "A" at 39.79,7.22 h1.52
  text "A" at 17.849,7.183 h1.52
  text "PB0" at 2.169,6.579 h1.3 r90
  text "PB3" at 59.195,6.578 h1.3 r90
  text "GND" at 56.1,4.775 h1.52
  text "GND" at 37.469,4.653 h1.52
  text "GND" at 0.85,4.525 h1.52
  text "GND" at 4.525,4.475 h1.52
  text "VCC" at 37.594,2.203 h1.52
  text "VCC" at 4.65,2.025 h1.52
  text "SW0" at 25.603,0.991 h1.52
  text "LED0" at 35.179,0.991 h1.52
Bottom Overlay:
  lines w0.4: 4.826,7.62 5.232,7.62 ; 4.826,10.16 5.232,10.16 ; 4.826,12.7 5.232,12.7 ; 4.826,15.24 5.232,15.24 ; 4.826,17.78 5.232,17.78 ; 4.826,20.32 5.232,20.32 ; 4.826,22.86 5.334,22.86 ; 4.826,25.4 5.232,25.4 ; 4.826,27.94 5.232,27.94 ; 4.826,30.48 5.232,30.48 ; 4.826,33.02 5.232,33.02 ; 4.826,35.56 5.232,35.56 ; 4.826,38.1 5.232,38.1 ; 4.826,40.64 5.232,40.64 ; 4.826,43.18 5.232,43.18 ; 4.826,45.72 5.334,45.72 ; 4.826,48.26 5.334,48.26 ; 4.826,50.8 5.334,50.8 ; 9.906,2.54 10.414,2.54 ; 9.906,5.08 10.414,5.08 ; 9.906,7.62 10.414,7.62 ; 9.906,10.16 10.414,10.16 ; 9.906,12.7 10.414,12.7 ; 9.906,15.24 10.414,15.24 ; 9.906,17.78 10.414,17.78 ; 9.906,20.32 10.414,20.32 ; 9.906,22.86 10.414,22.86 ; 9.906,25.4 10.414,25.4 ; 9.906,27.94 10.414,27.94 ; 9.906,30.48 10.414,30.48 ; 9.906,33.02 10.414,33.02 ; 9.906,35.56 10.414,35.56 ; 9.906,38.1 10.414,38.1 ; 9.906,40.64 10.414,40.64 ; 9.906,43.18 10.414,43.18 ; 9.906,45.72 10.414,45.72 ; 9.906,48.26 10.414,48.26 ; 9.906,50.8 10.414,50.8 ; 12.446,2.54 12.954,2.54 ; 12.446,5.08 12.954,5.08 ; 12.446,48.26 12.954,48.26 ; 12.446,50.8 12.954,50.8 ; 14.986,2.54 15.494,2.54 ; 14.986,5.08 15.494,5.08 ; 14.986,7.62 15.494,7.62 ; 14.986,10.16 15.494,10.16 ; 14.986,12.7 15.494,12.7 ; 14.986,15.24 15.494,15.24 ; 14.986,17.78 15.494,17.78 ; 14.986,20.32 15.494,20.32 ; 14.986,22.86 15.494,22.86 ; 14.986,25.4 15.494,25.4 ; 14.986,27.94 15.494,27.94 ; 14.986,30.48 15.494,30.48 ; 14.986,33.02 15.494,33.02 ; 14.986,35.56 15.494,35.56 ; 14.986,38.1 15.494,38.1 ; 14.986,40.64 15.494,40.64 ; 14.986,43.18 15.494,43.18 ; 14.986,45.72 15.494,45.72 ; 42.926,2.54 43.434,2.54 ; 42.926,5.08 43.434,5.08 ; 42.926,7.62 43.434,7.62 ; 42.926,10.16 43.434,10.16 ; 42.926,22.86 43.434,22.86 ; 42.926,25.4 43.434,25.4 ; 42.926,27.94 43.434,27.94 ; 42.926,30.48 43.434,30.48 ; 42.926,33.02 43.434,33.02 ; 42.926,35.56 43.434,35.56 ; 42.926,38.1 43.434,38.1 ; 42.926,40.64 43.434,40.64 ; 42.926,43.18 43.434,43.18 ; 42.926,45.72 43.434,45.72 ; 42.926,48.26 43.434,48.26 ; 42.926,50.8 43.434,50.8 ; 45.466,2.54 45.974,2.54 ; 45.466,5.08 45.974,5.08 ; 48.006,2.54 48.514,2.54 ; 48.006,5.08 48.514,5.08 ; 48.006,7.62 48.514,7.62 ; 48.006,10.16 48.514,10.16 ; 48.006,12.7 48.514,12.7 ; 48.006,15.24 48.514,15.24 ; 48.006,17.78 48.514,17.78 ; 48.006,20.32 48.514,20.32 ; 48.006,22.86 48.514,22.86 ; 48.006,25.4 48.514,25.4 ; 48.006,27.94 48.514,27.94 ; 48.006,30.48 48.514,30.48 ; 48.006,33.02 48.514,33.02 ; 48.006,35.56 48.514,35.56 ; 48.006,38.1 48.514,38.1 ; 48.006,40.64 48.514,40.64 ; 48.006,43.18 48.514,43.18 ; 48.006,45.72 48.514,45.72 ; 48.006,48.26 48.514,48.26 ; 48.006,50.8 48.514,50.8 ; 50.546,2.54 51.054,2.54 ; 50.546,5.08 51.054,5.08 ; 50.546,7.62 51.054,7.62 ; 50.546,10.16 51.054,10.16 ; 50.546,12.7 51.054,12.7 ; 50.546,15.24 51.054,15.24 ; 50.546,17.78 51.054,17.78 ; 50.546,20.32 51.054,20.32 ; 50.546,22.86 51.054,22.86 ; 50.546,25.4 51.054,25.4 ; 50.546,27.94 51.054,27.94 ; 50.546,35.56 51.054,35.56 ; 50.546,38.1 51.054,38.1 ; 50.546,40.64 51.054,40.64 ; 50.546,43.18 51.054,43.18 ; 50.546,45.72 51.054,45.72 ; 50.546,48.26 51.054,48.26 ; 50.546,50.8 51.054,50.8 ; 55.728,7.62 56.134,7.62 ; 55.728,10.16 56.134,10.16 ; 55.728,12.7 56.134,12.7 ; 55.728,15.24 56.134,15.24 ; 55.728,17.78 56.134,17.78 ; 55.728,20.32 56.134,20.32 ; 55.728,22.86 56.134,22.86 ; 55.728,25.4 56.134,25.4 ; 55.738,52.302 56.452,51.588 ; 55.75,29.45 56.464,28.736 ; 55.75,32 56.464,31.286 ; 55.75,34.5 56.464,33.786 ; 55.75,37.05 56.464,36.336 ; 55.75,39.6 56.464,38.886 ; 55.75,42.15 56.464,41.436 ; 55.75,44.7 56.464,43.986 ; 55.75,47.2 56.464,46.486 ; 55.75,49.75 56.464,49.036
  text "11" at 55.225,53.75 h1.52
  text "0" at 4.14,52.025 h1.52
  text "1" at 6.68,52.025 h1.52
  text "2" at 9.22,52.025 h1.52
  text "3" at 11.76,52.025 h1.52
  text "4" at 14.3,52.025 h1.52
  text "5" at 16.84,52.025 h1.52
  text "6" at 42.24,52.025 h1.52
  text "7" at 44.78,52.025 h1.52
  text "8" at 47.32,52.025 h1.52
  text "9" at 49.86,52.025 h1.52
  text "10" at 52.7,52.025 h1.52
  text "12" at 57.825,52.025 h1.52
  text "R" at 18.675,50.408 h1.52
  text "R" at 40.6,50.408 h1.52
  text "Q" at 18.675,47.774 h1.52
  text "Q" at 40.6,47.774 h1.52
  text "P" at 18.675,45.361 h1.52
  text "P" at 40.6,45.361 h1.52
  text "O" at 18.675,42.719 h1.52
  text "O" at 40.6,42.719 h1.52
  text "N" at 18.675,40.246 h1.52
  text "N" at 40.6,40.246 h1.52
  text "M" at 18.675,37.646 h1.52
  text "M" at 40.6,37.646 h1.52
  text "L" at 18.675,35.223 h1.52
  text "L" at 40.6,35.223 h1.52
  text "PC2" at 53,33.9 h1.1
  text "PC3" at 37.68,32.694 h1.52
  text "K" at 18.675,32.619 h1.52
  text "K" at 41.021,32.549 h1.52
  text "J" at 18.674,30.168 h1.52
  text "PC1" at 37.716,30.142 h1.52
  text "J" at 41.021,30.009 h1.52
  text "PC0" at 52.95,28.85 h1.1
  text "I" at 18.675,27.845 h1.52
  text "I" at 40.6,27.845 h1.52
  text "H" at 18.675,25.003 h1.52
  text "H" at 40.6,25.003 h1.52
  text "c" at 38.302,22.444 h5
  text "G" at 18.675,22.41 h1.52
  text "G" at 40.6,22.41 h1.52
  text "p" at 26.436,21.375 h6.5
  text "t" at 32.525,21.075 h7
  text "F" at 18.675,19.992 h1.52
  text "F" at 45.68,19.992 h1.52
  text "Atmel Corp © 2016" at 37.802,17.474 h2
  text "E" at 18.675,17.417 h1.52
  text "E" at 45.68,17.417 h1.52
  text "D" at 18.675,14.837 h1.52
  text "D" at 45.68,14.837 h1.52
  text "C" at 18.675,12.28 h1.52
  text "C" at 45.68,12.28 h1.52
  text "A08-2508 Rev 2" at 36.358,11.675 h2
  text "B" at 18.675,9.768 h1.52
  text "B" at 40.6,9.768 h1.52
  text "PC5" at 30.147,9.119 h1.52
  text "PC0" at 32.936,9.119 h1.52
  text "PC1" at 35.639,9.119 h1.52
  text "A" at 18.675,7.183 h1.52
  text "A" at 40.6,7.183 h1.52
  text "GND" at 20.689,4.609 h1.52
  text "GND" at 40.6,4.609 h1.52
  text "PC2" at 32.941,2.369 h1.52
  text "5V0" at 35.658,2.369 h1.52
  text "GND" at 30.099,2.35 h1.52
  text "VCC" at 20.548,2.069 h1.52
  text "VCC" at 40.6,2.069 h1.52
Mechanical 1:
  lines w0.1: 0,1 ccw(c1,1) 1,0 59,0 ccw(c59,1) 60,1 60,59 ccw(c59,59) 59,60 37,60 cw(c37,61) 36,61 36,74 ccw(c35,74) 35,75 25,75 ccw(c25,74) 24,74 24,61 cw(c23,61) 23,60 1,60 ccw(c1,59) 0,59 0,13.25 0,1
Mechanical 4:
  text "Mechanical Dimensions" at 11.008,85.381 h5
Mechanical 15:
  lines w0.3: 40.413,43.654 cw(c40.413,43.593) 40.455,43.636
Mechanical 16:
  lines w0.127: -159,-66.915 -153.92,-66.915 ; -159,3.745 -153.92,3.745 ; -159,74.23 -153.92,74.23 ; -109.724,-137.4 -109.724,-132.32 ; -109.724,139.46 -109.724,144.54 ; -65.7,139.46 -65.7,144.54 ; -60.575,-137.4 -60.575,-132.32 ; -16.525,139.46 -16.525,144.54 ; -11.426,-137.4 -11.426,-132.32 ; 37.85,-137.4 37.85,-132.32 ; 37.85,139.46 37.85,144.54 ; 86.999,-137.4 86.999,-132.32 ; 86.999,139.46 86.999,144.54 ; 115.32,-124.7 229.62,-124.7 ; 115.32,-117.08 229.62,-117.08 ; 115.32,-109.46 153.42,-109.46 ; 136.148,-137.4 136.148,-132.32 ; 136.148,139.46 136.148,144.54 ; 153.42,-132.32 153.42,-117.08 153.42,-101.84 ; 185.424,-137.4 185.424,-132.32 ; 185.424,139.46 185.424,144.54 ; 206.76,-132.32 206.76,-117.08 ; 229.62,-66.915 234.7,-66.915 ; 229.62,3.7 234.7,3.7 ; 229.62,74.185 234.7,74.185 ; 115.32,-132.32 115.32,-101.84 ; 115.32,-132.32 229.62,-132.32 ; 115.32,-132.32 79.76,-132.32 79.76,-101.84 115.32,-101.84 ; 115.32,-101.84 153.42,-101.84 ; 153.42,-101.84 229.62,-101.84 229.62,-132.32 ; 229.62,-132.32 229.62,139.46 -153.92,139.46 -153.92,-132.32 229.62,-132.32 ; -159,-137.4 234.7,-137.4 234.7,144.54 -159,144.54 -159,-137.4
  text "1" at -134.963,141.111 h0.67
  text "4" at 12.628,141.111 h0.67
  text "5" at 61.904,141.111 h0.67
  text "6" at 110.926,141.111 h0.67
  text "7" at 160.456,141.111 h0.67
  text "8" at 209.478,141.111 h0.67
  text "2" at -88.474,140.975 h0.67
  text "3" at -41.924,140.825 h0.67
  text "A" at -157.095,107.301 h0.67
  text "A" at 231.525,107.256 h0.67
  text "B" at 231.605,39.201 h0.67
  text "B" at -157.095,36.689 h0.67
  text "C" at -157.188,-31.488 h0.67
  text "C" at 231.975,-37.1 h0.67
  text "D" at -157.095,-104.202 h0.67
  text "D" at 231.525,-104.202 h0.67
  text "ENGINEER:" at 116.59,-104.38 h0.67
  text "TITLE:" at 154.69,-104.38 h0.67
  text "PCB DESIGNER:" at 116.59,-111.873 h0.67
  text "B" at 82.525,-116.65 h20
  text "DATE:" at 116.59,-119.62 h0.67
  text "PART NO.:" at 154.69,-119.62 h0.67
  text "REV:" at 208.03,-119.62 h0.67
  text "ATMEL NORWAY" at 82.575,-120.25 h0.67
  text "Vestre Rosten 79" at 82.545,-122.328 h0.67
  text ".PRINT_DATE" at 116.7,-123.5 h0.67
  text "N-7075 Tiller" at 82.545,-125.63 h0.67
  text "FILE NAME:" at 116.59,-127.24 h0.67
  text "DWG NO:" at 154.69,-127.24 h0.67
  text "SCALE:" at 208.03,-127.24 h0.67
  text ".PCB_FILE_NAME_NO_PATH" at 117.86,-130.288 h0.67
  text "2" at -85.34,-135.688 h0.67
  text "3" at -35.81,-135.688 h0.67
  text "4" at 13.212,-135.688 h0.67
  text "5" at 61.904,-135.688 h0.67
  text "6" at 110.926,-135.688 h0.67
  text "7" at 160.456,-135.688 h0.67
  text "8" at 209.478,-135.688 h0.67

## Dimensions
60,59 to 36,61 on Mechanical 4
0,0 to 57.65,57.65 on Mechanical 4
0,0 to 2.35,57.65 on Mechanical 4
2.35,57.65 to 0,0 on Mechanical 4
2.35,2.35 to 1,0 on Mechanical 4
0,0 to 60,1 on Mechanical 4
60,0 to 59,60 on Mechanical 4
24,61 to 0,59 on Mechanical 4
36,74 to 24,74 on Mechanical 4
59,60 to 35,75 on Mechanical 4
